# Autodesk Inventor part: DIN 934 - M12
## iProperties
Created: 2006-02
Part Number: DIN 934 - M12
Material: Steel, Mild
Description: Hex Nut
Document SubType Name: Modeling
Standard: DIN 934
Designer: Andy Moles
Standards Organization: DIN
Language: en-US
Size Designation: M12
Categories: <MemberInstance><Categories><Category DisplayName="Fasteners" InternalName="e4da775c-781d-43d5-af7c-5136215cf5a6" Mnemonic="FSTN"><Category DisplayName="Nuts" I
Density: 7.86 g/cm^3
Mass: 17.5637 g
Surface Area: 13.3413 cm^2
Volume: 2.23456 cm^3
Author: Andy Moles
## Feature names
1. Body [Extrusion]
2. Chamfer1 [Revolution]
3. Thread [Hole]
4. Chamfer2
5. Chamfer3
